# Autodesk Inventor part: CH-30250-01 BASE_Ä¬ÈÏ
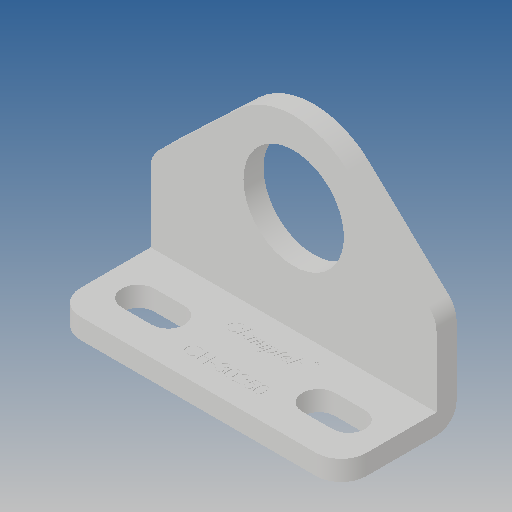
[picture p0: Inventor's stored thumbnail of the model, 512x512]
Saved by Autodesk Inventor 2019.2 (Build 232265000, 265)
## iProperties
Created: 2010-06
Part Number: CH-30250-01 BASE_Ä¬ÈÏ
Material: Ogólny
Document SubType Name: Modeling
Designer: CADENGINEERING4
Density: 1 g/cm^3
Appearance: Domyślna
Author: CADENGINEERING4
Revision Number: ÈÎºÎ
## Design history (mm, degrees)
feature "NONE"
node "Bryła1"
